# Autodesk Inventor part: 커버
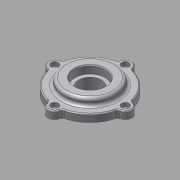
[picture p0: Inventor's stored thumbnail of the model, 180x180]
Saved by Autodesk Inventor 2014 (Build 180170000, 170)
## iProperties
Company: 한국ATC센터
Created: 2015-12
Part Number: 커버
Document SubType Name: Modeling
Designer: mdu
Density: 2.71 g/cm^3
Material: 알루미늄 6061
Appearance: 알루미늄 - 평지
Author: mdu
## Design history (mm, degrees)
sketch "스케치1"
  geometry: C1 r 1.621 at (0, 6.75) reference; C2 r 1.621 at (-37, -30.25) reference; C3 r 1.621 at (0, -67.25) reference; C4 r 1.621 at (37, -30.25) reference; C5 r 10 at (0, -30.25) reference; C6 r 12 at (0, -30.25); C7 r 24.5 at (0, -30.25) reference; A1 r 3 centre (-38.77, -20.408) between (-38.239, -23.361) and (-35.862, -21.146) reference; A2 r 7 centre (-37, -30.25) between (-38.239, -23.361) and (-38.239, -37.139) reference; A3 r 3 centre (-38.77, -40.092) between (-35.862, -39.354) and (-38.239, -37.139) reference; A4 r 37 centre (0, -30.25) between (-35.862, -39.354) and (-9.104, -66.113) reference; A5 r 3 centre (-9.842, -69.02) between (-6.889, -68.489) and (-9.104, -66.113) reference; A6 r 7 centre (0, -67.25) between (-6.889, -68.489) and (6.889, -68.489) reference; A7 r 3 centre (9.842, -69.02) between (9.104, -66.112) and (6.889, -68.489) reference; A8 r 37 centre (0, -30.25) between (9.104, -66.112) and (35.863, -39.354) reference; A9 r 3 centre (38.77, -40.092) between (38.239, -37.139) and (35.863, -39.354) reference; A10 r 7 centre (37, -30.25) between (38.239, -37.139) and (38.239, -23.361) reference; A11 r 3 centre (38.77, -20.408) between (35.863, -21.146) and (38.239, -23.361) reference; A12 r 37 centre (0, -30.25) between (35.863, -21.146) and (9.104, 5.612) reference; A13 r 3 centre (9.842, 8.52) between (6.889, 7.989) and (9.104, 5.612) reference; A14 r 7 centre (0, 6.75) between (6.889, 7.989) and (-6.889, 7.989) reference; A15 r 3 centre (-9.842, 8.52) between (-9.104, 5.612) and (-6.889, 7.989) reference; A16 r 37 centre (0, -30.25) between (-9.104, 5.612) and (-35.862, -21.146) reference; 1 further point
  constraints: 1 centre point, 1 coincident
  dimensions: "d2" = 2 radial gap between concentric circles of C6 C5
extrude "돌출1" new body sketch "스케치1" distance "d0" = 8; taper "d1" = 0 deg
sketch "스케치2"
  geometry: C1 r 23.5 at (0, -30.25) reference; C2 r 12 at (0, -30.25) reference; 1 further point
extrude "돌출2" join sketch "스케치2" distance "d4" = 5; taper "d5" = 0 deg
sketch "스케치3"
  geometry: C1 r 23.5 at (0, 0) reference; C2 r 20.5 at (0, 0); 1 further point
  constraints: 1 centre point
  dimensions: "d6" = 3 radial gap between concentric circles of C2 C1
node "작업 평면1"
extrude "돌출3" join sketch "스케치3" stored distance "d7" = 5; taper "d8" = 0 deg
fillet "모깎기1" dims "d9" = 3
sketch "스케치4"
  geometry: C1 r 12 at (0, -30.25) reference; C2 r 27 at (0, -30.25); 1 further point
  constraints: 1 centre point
  dimensions: "d10" = 15 radial gap between concentric circles of C1 C2
extrude "돌출4" join sketch "스케치4" distance "d11" = 7; taper "d12" = 0 deg
fillet "모깎기2" dims "d13" = 3
chamfer "모따기1" distance "d14" = 1; stored, may be unused: second distance "d15" = 2, angle "d16" = 45 deg
node "작업점1"
  node "작업축1"
chamfer "모따기2" distance "d24" = 1; stored, may be unused: second distance "d25" = 2, angle "d26" = 45 deg
hole "구멍6" diameter "d43" = 4.5; stored, may be unused: countersink angle "d47" = 90 deg, drill point angle "d49" = 118 deg; dims "d41" = 10, "d42" = 10, "d44" = 6, "d45" = 8, "d46" = 4.4, "d48" = 8
sketch "스케치8"
  geometry: C1 r 12 at (0, 0) reference; C2 r 16 at (0, 0); 1 further point
  constraints: 1 centre point, 1 coincident
  dimensions: "d53" = 32 diameter of C2
extrude "돌출5" cut sketch "스케치8" distance "d54" = 8.3; taper "d55" = 0 deg
fillet "모깎기3" dims "d56" = 0.3
chamfer "모따기3" distance "d57" = 1.2; stored, may be unused: second distance "d58" = 2, angle "d59" = 30 deg
node "솔리드1"
pattern_circular "원형 패턴1" dims angle "d51" = 360 deg
node "참조1"
node "참조2"
